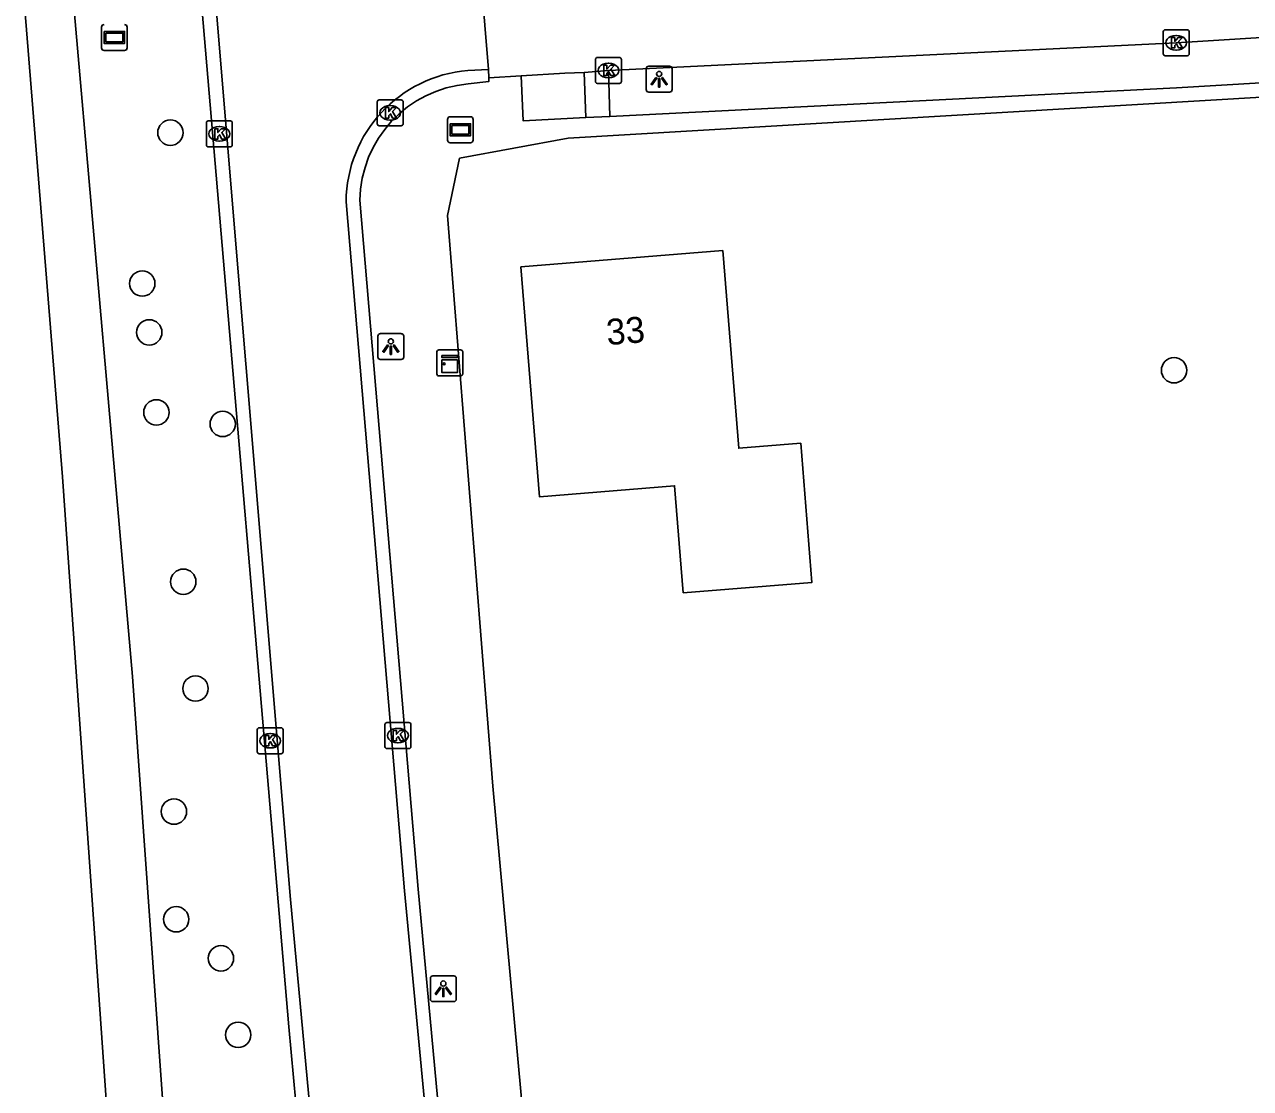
# Model space of a CAD drawing. Extents: x 162675 to 163482, y 379761 to 381227.
# Drawn here: x 163097.79 to 163145.1, y 380672.29 to 380713.34 of the extents above; entities that cross this region are included whole.
import ezdxf

# ---------------------------------------------------------------- set-up
doc = ezdxf.new("R2010")
doc.units = 0
for name, color, linetype in [('IMGEO_Boom', 7, 'Continuous'), ('IMGEO_Groenvoorziening', 7, 'Continuous'), ('IMGEO_Kast', 7, 'Continuous'), ('IMGEO_Kolk', 7, 'Continuous'), ('IMGEO_Lichtpunt', 7, 'Continuous'), ('IMGEO_Pand', 7, 'Continuous'), ('IMGEO_Pand_nummerreeks', 7, 'Continuous'), ('IMGEO_Parkeervlak_halfverhard', 7, 'Continuous'), ('IMGEO_Rijbaan_lokaal_gesloten', 7, 'Continuous'), ('IMGEO_Rijbaan_lokaal_open', 7, 'Continuous'), ('IMGEO_Straatnaambord', 7, 'Continuous'), ('IMGEO_Verklikker', 7, 'Continuous'), ('IMGEO_Voetpad_open', 7, 'Continuous')]:
    doc.layers.add(name, color=color, linetype=linetype)

msp = doc.modelspace()

# ---------------------------------------------------------------- linework, layer by layer
at = {"layer": 'IMGEO_Boom'}
for centre in [(163103.422, 380709.163), (163102.337, 380703.343), (163102.606, 380701.459), (163142.148, 380699.996), (163102.882, 380698.371), (163105.439, 380697.926), (163103.92, 380691.838), (163104.39, 380687.716), (163103.559, 380682.97), (163103.647, 380678.814), (163105.372, 380677.309), (163106.037, 380674.357)]:
    msp.add_circle(centre, 0.489, dxfattribs=at)
at = {"layer": 'IMGEO_Groenvoorziening'}
msp.add_lwpolyline([(163165.538, 380711.722), (163118.769, 380708.949), (163114.577, 380708.178), (163114.12, 380705.969), (163115.857, 380683.956), (163117.643, 380664.6), (163117.707, 380663.313)], dxfattribs=at)
at = {"layer": 'IMGEO_Kast'}
for p, q in [((163113.778, 380700.779), (163114.619, 380700.779)), ((163114.619, 380700.779), (163113.778, 380700.779)), ((163114.703, 380700.704), (163114.703, 380699.863)), ((163114.703, 380699.863), (163114.703, 380700.704)), ((163113.703, 380699.854), (163113.703, 380700.695)), ((163113.703, 380700.695), (163113.703, 380699.854)), ((163114.628, 380699.779), (163113.787, 380699.779)), ((163113.787, 380699.779), (163114.628, 380699.779))]:
    msp.add_line(p, q, dxfattribs=at)
for points in [[(163113.898, 380700.569), (163114.498, 380700.569), (163114.498, 380700.484), (163113.898, 380700.484), (163113.898, 380700.569)], [(163113.898, 380700.394), (163114.498, 380700.394), (163114.498, 380699.905), (163113.898, 380699.905), (163113.898, 380700.394)]]:
    msp.add_lwpolyline(points, dxfattribs=at)
msp.add_circle((163113.982, 380700.243), 0.0377, dxfattribs=at)
for centre, start, end in [((163113.781, 380700.701), 92.4484, 184.2845), ((163113.781, 380700.701), 92.4484, 184.2845), ((163114.625, 380700.701), 2.4484, 94.2845), ((163114.625, 380700.701), 2.4484, 94.2845), ((163113.781, 380699.857), 182.4484, 274.2845), ((163113.781, 380699.857), 182.4484, 274.2845), ((163114.625, 380699.857), 272.4484, 4.2845), ((163114.625, 380699.857), 272.4484, 4.2845)]:
    msp.add_arc(centre, 0.0779, start, end, dxfattribs=at)
at = {"layer": 'IMGEO_Kolk'}
for p, q in [((163141.731, 380712.206), (163141.731, 380713.058)), ((163141.806, 380713.132), (163142.658, 380713.132)), ((163142.732, 380713.058), (163142.732, 380712.206)), ((163142.219, 380712.912), (163142.244, 380712.912)), ((163119.898, 380712.063), (163120.75, 380712.063)), ((163142.658, 380712.132), (163141.806, 380712.132)), ((163142.242, 380712.352), (163142.217, 380712.352)), ((163119.823, 380711.137), (163119.823, 380711.989)), ((163120.311, 380711.843), (163120.336, 380711.843)), ((163120.824, 380711.989), (163120.824, 380711.137)), ((163120.334, 380711.283), (163120.309, 380711.283)), ((163120.75, 380711.063), (163119.898, 380711.063)), ((163111.402, 380709.502), (163111.402, 380710.354)), ((163111.477, 380710.428), (163112.329, 380710.428)), ((163111.89, 380710.208), (163111.915, 380710.208)), ((163112.403, 380710.354), (163112.403, 380709.502)), ((163104.81, 380708.691), (163104.81, 380709.543)), ((163104.885, 380709.617), (163105.737, 380709.617)), ((163105.298, 380709.397), (163105.323, 380709.397)), ((163105.811, 380709.543), (163105.811, 380708.691)), ((163112.329, 380709.428), (163111.477, 380709.428)), ((163111.913, 380709.648), (163111.888, 380709.648)), ((163105.321, 380708.837), (163105.296, 380708.837)), ((163105.737, 380708.617), (163104.885, 380708.617)), ((163106.77, 380685.278), (163106.77, 380686.13)), ((163106.845, 380686.204), (163107.697, 380686.204)), ((163107.771, 380686.13), (163107.771, 380685.278)), ((163111.701, 380685.476), (163111.701, 380686.328)), ((163111.776, 380686.402), (163112.628, 380686.402)), ((163112.189, 380686.182), (163112.214, 380686.182)), ((163112.702, 380686.328), (163112.702, 380685.476)), ((163107.258, 380685.984), (163107.283, 380685.984)), ((163112.212, 380685.622), (163112.187, 380685.622)), ((163107.697, 380685.204), (163106.845, 380685.204)), ((163107.281, 380685.424), (163107.256, 380685.424)), ((163112.628, 380685.402), (163111.776, 380685.402))]:
    msp.add_line(p, q, dxfattribs=at)
for points in [[(163141.731, 380712.206), (163141.731, 380713.058)], [(163141.806, 380713.132), (163142.658, 380713.132)], [(163142.732, 380713.058), (163142.732, 380712.206)], [(163142.052, 380712.832), (163142.175, 380712.832), (163142.175, 380712.681), (163142.305, 380712.832), (163142.469, 380712.832), (163142.323, 380712.681), (163142.476, 380712.432), (163142.324, 380712.432), (163142.239, 380712.596), (163142.175, 380712.529), (163142.175, 380712.432), (163142.052, 380712.432), (163142.052, 380712.832)], [(163119.898, 380712.063), (163120.75, 380712.063)], [(163142.658, 380712.132), (163141.806, 380712.132)], [(163119.823, 380711.137), (163119.823, 380711.989)], [(163120.144, 380711.763), (163120.267, 380711.763), (163120.267, 380711.612), (163120.397, 380711.763), (163120.561, 380711.763), (163120.415, 380711.612), (163120.568, 380711.363), (163120.416, 380711.363), (163120.331, 380711.527), (163120.267, 380711.46), (163120.267, 380711.363), (163120.144, 380711.363), (163120.144, 380711.763)], [(163120.824, 380711.989), (163120.824, 380711.137)], [(163120.75, 380711.063), (163119.898, 380711.063)], [(163111.402, 380709.502), (163111.402, 380710.354)], [(163111.477, 380710.428), (163112.329, 380710.428)], [(163112.403, 380710.354), (163112.403, 380709.502)], [(163111.723, 380710.128), (163111.846, 380710.128), (163111.846, 380709.977), (163111.976, 380710.128), (163112.14, 380710.128), (163111.994, 380709.977), (163112.147, 380709.728), (163111.995, 380709.728), (163111.91, 380709.892), (163111.846, 380709.825), (163111.846, 380709.728), (163111.723, 380709.728), (163111.723, 380710.128)], [(163104.81, 380708.691), (163104.81, 380709.543)], [(163104.885, 380709.617), (163105.737, 380709.617)], [(163105.131, 380709.317), (163105.254, 380709.317), (163105.254, 380709.166), (163105.384, 380709.317), (163105.548, 380709.317), (163105.402, 380709.166), (163105.555, 380708.917), (163105.403, 380708.917), (163105.318, 380709.081), (163105.254, 380709.014), (163105.254, 380708.917), (163105.131, 380708.917), (163105.131, 380709.317)], [(163105.811, 380709.543), (163105.811, 380708.691)], [(163112.329, 380709.428), (163111.477, 380709.428)], [(163105.737, 380708.617), (163104.885, 380708.617)], [(163106.77, 380685.278), (163106.77, 380686.13)], [(163106.845, 380686.204), (163107.697, 380686.204)], [(163107.771, 380686.13), (163107.771, 380685.278)], [(163111.701, 380685.476), (163111.701, 380686.328)], [(163111.776, 380686.402), (163112.628, 380686.402)], [(163112.022, 380686.102), (163112.145, 380686.102), (163112.145, 380685.951), (163112.275, 380686.102), (163112.439, 380686.102), (163112.293, 380685.951), (163112.446, 380685.702), (163112.294, 380685.702), (163112.209, 380685.866), (163112.145, 380685.799), (163112.145, 380685.702), (163112.022, 380685.702), (163112.022, 380686.102)], [(163112.702, 380686.328), (163112.702, 380685.476)], [(163107.091, 380685.904), (163107.214, 380685.904), (163107.214, 380685.753), (163107.344, 380685.904), (163107.508, 380685.904), (163107.362, 380685.753), (163107.515, 380685.504), (163107.363, 380685.504), (163107.278, 380685.668), (163107.214, 380685.601), (163107.214, 380685.504), (163107.091, 380685.504), (163107.091, 380685.904)], [(163107.697, 380685.204), (163106.845, 380685.204)], [(163112.628, 380685.402), (163111.776, 380685.402)]]:
    msp.add_lwpolyline(points, dxfattribs=at)
for centre, start, end in [((163141.808, 380713.056), 91.552, 178.448), ((163141.808, 380713.056), 91.552, 178.448), ((163142.656, 380713.056), 1.552, 88.448), ((163142.656, 380713.056), 1.552, 88.448), ((163119.9, 380711.987), 91.552, 178.448), ((163119.9, 380711.987), 91.552, 178.448), ((163120.748, 380711.987), 1.552, 88.448), ((163120.748, 380711.987), 1.552, 88.448), ((163141.808, 380712.208), 181.552, 268.448), ((163141.808, 380712.208), 181.552, 268.448), ((163142.656, 380712.208), 271.552, 358.448), ((163142.656, 380712.208), 271.552, 358.448), ((163119.9, 380711.139), 181.552, 268.448), ((163119.9, 380711.139), 181.552, 268.448), ((163120.748, 380711.139), 271.552, 358.448), ((163120.748, 380711.139), 271.552, 358.448), ((163111.479, 380710.352), 91.552, 178.448), ((163111.479, 380710.352), 91.552, 178.448), ((163112.327, 380710.352), 1.552, 88.448), ((163112.327, 380710.352), 1.552, 88.448), ((163104.887, 380709.541), 91.552, 178.448), ((163104.887, 380709.541), 91.552, 178.448), ((163105.735, 380709.541), 1.552, 88.448), ((163105.735, 380709.541), 1.552, 88.448), ((163111.479, 380709.504), 181.552, 268.448), ((163111.479, 380709.504), 181.552, 268.448), ((163112.327, 380709.504), 271.552, 358.448), ((163112.327, 380709.504), 271.552, 358.448), ((163104.887, 380708.693), 181.552, 268.448), ((163104.887, 380708.693), 181.552, 268.448), ((163105.735, 380708.693), 271.552, 358.448), ((163105.735, 380708.693), 271.552, 358.448), ((163106.847, 380686.128), 91.552, 178.448), ((163106.847, 380686.128), 91.552, 178.448), ((163107.695, 380686.128), 1.552, 88.448), ((163107.695, 380686.128), 1.552, 88.448), ((163111.778, 380686.326), 91.552, 178.448), ((163111.778, 380686.326), 91.552, 178.448), ((163112.626, 380686.326), 1.552, 88.448), ((163112.626, 380686.326), 1.552, 88.448), ((163106.847, 380685.28), 181.552, 268.448), ((163106.847, 380685.28), 181.552, 268.448), ((163107.695, 380685.28), 271.552, 358.448), ((163107.695, 380685.28), 271.552, 358.448), ((163111.778, 380685.478), 181.552, 268.448), ((163111.778, 380685.478), 181.552, 268.448), ((163112.626, 380685.478), 271.552, 358.448), ((163112.626, 380685.478), 271.552, 358.448)]:
    msp.add_arc(centre, 0.0765, start, end, dxfattribs=at)
for centre, major_axis, ratio, start_param, end_param in [((163142.218, 380712.632), (-0.387, 0.002), 0.722429, 4.712389, 7.853982), ((163142.243, 380712.632), (-0.39, 0.002), 0.717154, 1.570796, 4.712389), ((163120.31, 380711.563), (-0.387, 0.002), 0.722429, 4.712389, 7.853982), ((163120.335, 380711.563), (-0.39, 0.002), 0.717154, 1.570796, 4.712389), ((163111.889, 380709.928), (-0.387, 0.002), 0.722429, 4.712389, 7.853982), ((163111.914, 380709.928), (-0.39, 0.002), 0.717154, 1.570796, 4.712389), ((163105.297, 380709.117), (-0.387, 0.002), 0.722429, 4.712389, 7.853982), ((163105.322, 380709.117), (-0.39, 0.002), 0.717154, 1.570796, 4.712389), ((163112.188, 380685.902), (-0.387, 0.002), 0.722429, 4.712389, 7.853982), ((163112.213, 380685.902), (-0.39, 0.002), 0.717154, 1.570796, 4.712389), ((163107.257, 380685.704), (-0.387, 0.002), 0.722429, 4.712389, 7.853982), ((163107.282, 380685.704), (-0.39, 0.002), 0.717154, 1.570796, 4.712389)]:
    msp.add_ellipse(centre, major_axis=major_axis, ratio=ratio, start_param=start_param, end_param=end_param, dxfattribs=at)
at = {"layer": 'IMGEO_Lichtpunt'}
for p, q in [((163121.782, 380711.631), (163121.782, 380710.824)), ((163121.782, 380711.631), (163121.782, 380710.824)), ((163122.684, 380711.726), (163121.876, 380711.726)), ((163122.684, 380711.726), (163121.876, 380711.726)), ((163122.778, 380710.824), (163122.778, 380711.631)), ((163122.778, 380710.824), (163122.778, 380711.631)), ((163121.876, 380710.73), (163122.684, 380710.73)), ((163121.876, 380710.73), (163122.684, 380710.73)), ((163111.428, 380701.314), (163111.428, 380700.507)), ((163111.428, 380701.314), (163111.428, 380700.507)), ((163112.33, 380701.409), (163111.522, 380701.409)), ((163112.33, 380701.409), (163111.522, 380701.409)), ((163112.424, 380700.507), (163112.424, 380701.314)), ((163112.424, 380700.507), (163112.424, 380701.314)), ((163111.522, 380700.413), (163112.33, 380700.413)), ((163111.522, 380700.413), (163112.33, 380700.413)), ((163114.356, 380676.634), (163113.548, 380676.634)), ((163114.356, 380676.634), (163113.548, 380676.634)), ((163113.454, 380676.539), (163113.454, 380675.732)), ((163113.454, 380676.539), (163113.454, 380675.732)), ((163114.45, 380675.732), (163114.45, 380676.539)), ((163114.45, 380675.732), (163114.45, 380676.539)), ((163113.548, 380675.638), (163114.356, 380675.638)), ((163113.548, 380675.638), (163114.356, 380675.638))]:
    msp.add_line(p, q, dxfattribs=at)
for points in [[(163122.156, 380711.295), (163122.195, 380711.267), (163122.007, 380711.005), (163121.969, 380711.032), (163122.156, 380711.295)], [(163122.258, 380711.247), (163122.305, 380711.247), (163122.305, 380710.925), (163122.258, 380710.925), (163122.258, 380711.247)], [(163122.368, 380711.267), (163122.406, 380711.294), (163122.593, 380711.032), (163122.554, 380711.004), (163122.368, 380711.267)], [(163111.802, 380700.978), (163111.841, 380700.95), (163111.653, 380700.688), (163111.615, 380700.715), (163111.802, 380700.978)], [(163111.904, 380700.93), (163111.951, 380700.93), (163111.951, 380700.608), (163111.904, 380700.608), (163111.904, 380700.93)], [(163112.014, 380700.95), (163112.052, 380700.977), (163112.239, 380700.715), (163112.2, 380700.687), (163112.014, 380700.95)], [(163113.828, 380676.203), (163113.867, 380676.175), (163113.679, 380675.913), (163113.641, 380675.94), (163113.828, 380676.203)], [(163113.93, 380676.155), (163113.977, 380676.155), (163113.977, 380675.833), (163113.93, 380675.833), (163113.93, 380676.155)], [(163114.04, 380676.175), (163114.078, 380676.202), (163114.265, 380675.94), (163114.226, 380675.912), (163114.04, 380676.175)]]:
    msp.add_lwpolyline(points, dxfattribs=at)
for centre in [(163122.281, 380711.429), (163111.927, 380701.112), (163113.953, 380676.337)]:
    msp.add_circle(centre, 0.0994, dxfattribs=at)
for centre, start, end in [((163121.876, 380711.631), 90, 180), ((163121.876, 380711.631), 90, 180), ((163122.684, 380711.631), 0, 90), ((163122.684, 380711.631), 0, 90), ((163121.876, 380710.824), 180, 270), ((163121.876, 380710.824), 180, 270), ((163122.684, 380710.824), 270, 0), ((163122.684, 380710.824), 270, 360), ((163111.522, 380701.314), 90, 180), ((163111.522, 380701.314), 90, 180), ((163112.33, 380701.314), 0, 90), ((163112.33, 380701.314), 0, 90), ((163111.522, 380700.507), 180, 270), ((163111.522, 380700.507), 180, 270), ((163112.33, 380700.507), 270, 0), ((163112.33, 380700.507), 270, 360), ((163113.548, 380676.539), 90, 180), ((163113.548, 380676.539), 90, 180), ((163114.356, 380676.539), 0, 90), ((163114.356, 380676.539), 0, 90), ((163113.548, 380675.732), 180, 270), ((163113.548, 380675.732), 180, 270), ((163114.356, 380675.732), 270, 0), ((163114.356, 380675.732), 270, 360)]:
    msp.add_arc(centre, 0.0946, start, end, dxfattribs=at)
at = {"layer": 'IMGEO_Pand'}
msp.add_lwpolyline([(163123.212, 380691.412), (163122.877, 380695.542), (163117.662, 380695.119), (163116.944, 380703.984), (163124.734, 380704.615), (163125.352, 380696.988), (163127.743, 380697.181), (163128.178, 380691.814), (163123.212, 380691.412)], dxfattribs=at)
at = {"layer": 'IMGEO_Parkeervlak_halfverhard'}
for points in [[(163119.45, 380709.752), (163117.031, 380709.623), (163116.953, 380711.361)], [(163152.219, 380711.484), (163142.245, 380710.899), (163120.382, 380709.791)]]:
    msp.add_lwpolyline(points, dxfattribs=at)
at = {"layer": 'IMGEO_Rijbaan_lokaal_gesloten'}
for points in [[(163101.152, 380762.413), (163108.051, 380679.583), (163111.151, 380646.231)], [(163115.281, 380716.591), (163115.697, 380711.596)], [(163120.324, 380711.563), (163142.232, 380712.632), (163152.095, 380713.243)], [(163115.697, 380711.596), (163114.9, 380711.56)], [(163115.709, 380711.284), (163115.697, 380711.596)], [(163116.953, 380711.361), (163115.709, 380711.284)], [(163116.953, 380711.361), (163118.64, 380711.465), (163119.381, 380711.482)], [(163119.381, 380711.482), (163120.324, 380711.563)], [(163110.203, 380706.499), (163112.449, 380679.916), (163116.651, 380635.796)]]:
    msp.add_lwpolyline(points, dxfattribs=at)
msp.add_arc((163115.306, 380706.473), 5.103, 94.5623, 179.7103, dxfattribs=at)
at = {"layer": 'IMGEO_Rijbaan_lokaal_open'}
for points in [[(163108.355, 380670.753), (163107.991, 380674.665), (163104.682, 380713.401), (163104.584, 380714.593)], [(163115.709, 380711.284), (163115.715, 380711.141), (163114.917, 380711.042)], [(163110.734, 380706.554), (163112.985, 380679.977), (163114.376, 380665.012)]]:
    msp.add_lwpolyline(points, dxfattribs=at)
msp.add_arc((163115.301, 380706.491), 4.568, 94.8247, 179.2044, dxfattribs=at)
at = {"layer": 'IMGEO_Straatnaambord'}
for p, q in [((163100.763, 380712.436), (163100.763, 380713.236)), ((163100.763, 380713.236), (163100.763, 380712.436)), ((163101.753, 380713.236), (163101.753, 380712.436)), ((163101.753, 380712.436), (163101.753, 380713.236)), ((163101.653, 380712.336), (163100.863, 380712.336)), ((163100.863, 380712.336), (163101.653, 380712.336))]:
    msp.add_line(p, q, dxfattribs=at)
for points in [[(163100.864, 380713.068), (163101.652, 380713.068), (163101.652, 380712.604), (163100.864, 380712.604), (163100.864, 380713.068)], [(163100.929, 380713.003), (163100.929, 380712.669), (163101.587, 380712.669), (163101.587, 380713.003), (163100.929, 380713.003)]]:
    msp.add_lwpolyline(points, dxfattribs=at)
for centre, start, end in [((163100.863, 380713.236), 90, 180), ((163100.863, 380713.236), 90, 180), ((163101.653, 380713.236), 0, 90), ((163101.653, 380713.236), 360, 90), ((163100.863, 380712.436), 180, 270), ((163100.863, 380712.436), 180, 270), ((163101.653, 380712.436), 270, 0), ((163101.653, 380712.436), 270, 0)]:
    msp.add_arc(centre, 0.1, start, end, dxfattribs=at)
at = {"layer": 'IMGEO_Verklikker'}
for p, q in [((163114.214, 380709.777), (163115.004, 380709.777)), ((163115.004, 380709.777), (163114.214, 380709.777)), ((163114.114, 380708.877), (163114.114, 380709.677)), ((163114.114, 380709.677), (163114.114, 380708.877)), ((163115.104, 380709.677), (163115.104, 380708.877)), ((163115.104, 380708.877), (163115.104, 380709.677)), ((163115.004, 380708.777), (163114.214, 380708.777)), ((163114.214, 380708.777), (163115.004, 380708.777))]:
    msp.add_line(p, q, dxfattribs=at)
for points in [[(163114.215, 380709.509), (163115.003, 380709.509), (163115.003, 380709.045), (163114.215, 380709.045), (163114.215, 380709.509)], [(163114.28, 380709.444), (163114.28, 380709.11), (163114.938, 380709.11), (163114.938, 380709.444), (163114.28, 380709.444)]]:
    msp.add_lwpolyline(points, dxfattribs=at)
for centre, start, end in [((163114.214, 380709.677), 90, 180), ((163114.214, 380709.677), 90, 180), ((163115.004, 380709.677), 0, 90), ((163115.004, 380709.677), 360, 90), ((163114.214, 380708.877), 180, 270), ((163114.214, 380708.877), 180, 270), ((163115.004, 380708.877), 270, 0), ((163115.004, 380708.877), 270, 0)]:
    msp.add_arc(centre, 0.1, start, end, dxfattribs=at)
at = {"layer": 'IMGEO_Voetpad_open'}
for points in [[(163101.186, 380668.378), (163101.16, 380668.743), (163099.255, 380695.881), (163097.801, 380713.922), (163097.793, 380714.023)], [(163099.679, 380714.181), (163101.96, 380688.185), (163103.318, 380669.012), (163103.34, 380668.7)], [(163119.381, 380711.482), (163119.45, 380709.752)], [(163120.382, 380709.791), (163120.324, 380711.563)], [(163120.382, 380709.791), (163119.45, 380709.752)]]:
    msp.add_lwpolyline(points, dxfattribs=at)

# ---------------------------------------------------------------- texts
at = {"layer": 'IMGEO_Pand_nummerreeks'}
msp.add_text('33', height=1, rotation=4.6309, dxfattribs=at).set_placement((163120.28, 380700.964))

doc.saveas('drawing.dxf')
